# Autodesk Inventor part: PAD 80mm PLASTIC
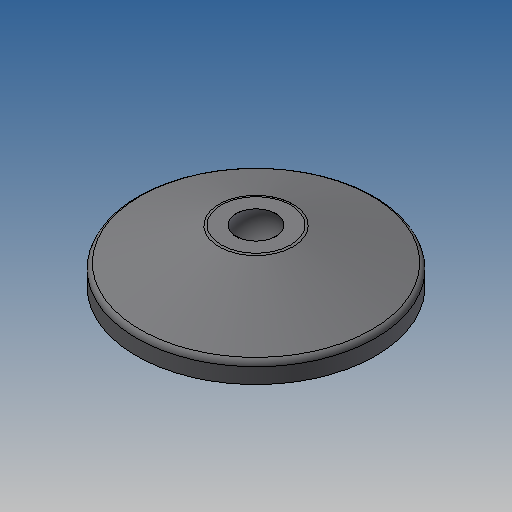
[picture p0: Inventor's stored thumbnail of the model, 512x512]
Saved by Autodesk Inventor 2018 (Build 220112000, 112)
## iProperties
Created: 2007-03
Part Number: PAD 80mm PLASTIC
Document SubType Name: Modeling
Designer: Andy Moles
Material: ABS Plastic
Density: 1.06 g/cm^3
Mass: 40.5634 g
Surface Area: 136.746 cm^2
Volume: 38.2674 cm^3
Appearance: Light Gray
Author: Andy Moles
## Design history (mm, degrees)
sketch "Sketch1"
  geometry: L1 (0, 0)-(40, 0); L2 (40, 0)-(40, 5.159); L3 (0, 0)-(0, 18); L4 (6.633, 18)-(11.605, 18); L5 (38.76, 7.009)-(12.365, 17.85); L6 (0, 0)-(0, 7); A1 r 7.5 centre (0, 14.5) between (0, 7) and (6.633, 18); A2 r 2 centre (11.605, 16) between (12.365, 17.85) and (11.605, 18); A3 r 2 centre (38, 5.159) between (40, 5.159) and (38.76, 7.009); 2 further points
  constraints: 12 end point, 6 point on circle, 6 point on line, 4 tangent, 3 centre point, 2 perpendicular, 1 collinear, 1 equal radius, 1 horizontal, 1 parallel
  dimensions: "d0" = 40 distance of L1.start L1.end; "d1" = 6.5 distance of L1.end point (40, 6.5); "d2" = 18 distance of L1.start L3.end; "d3" = 15 diameter of A1; "d4" = 3.5 distance of A1.centre L3.end; "d5" = 12 horizontal distance of point (12, 18) L1.start; "d6" = 2 radius of A2; "d14" = 18 distance between parallel lines of L4 L1
revolve "Revolution1" sketch "Sketch1" stored, may be unused: angle "d7" = 90 deg
sketch "Sketch2"
  geometry: C1 r 40 at (0, 0) reference; C2 r 7.5 at (0, 0)
  constraints: 1 centre point, 1 coincident
  dimensions: "d8" = 15 diameter of C2
extrude "Extrusion1" cut sketch "Sketch2" distance "d9" = 1; taper "d10" = 0 deg
sketch "Sketch3"
  geometry: C1 r 7.5 at (0, 0) reference; C2 r 40 at (0, 0) reference; C3 r 36 at (0, 0)
  constraints: 1 centre point, 1 coincident
  dimensions: "d11" = 4 radial gap between concentric circles of C2 C3
extrude "Extrusion2" cut sketch "Sketch3" distance "d12" = 5; taper "d13" = 0 deg
body "Solid1"
